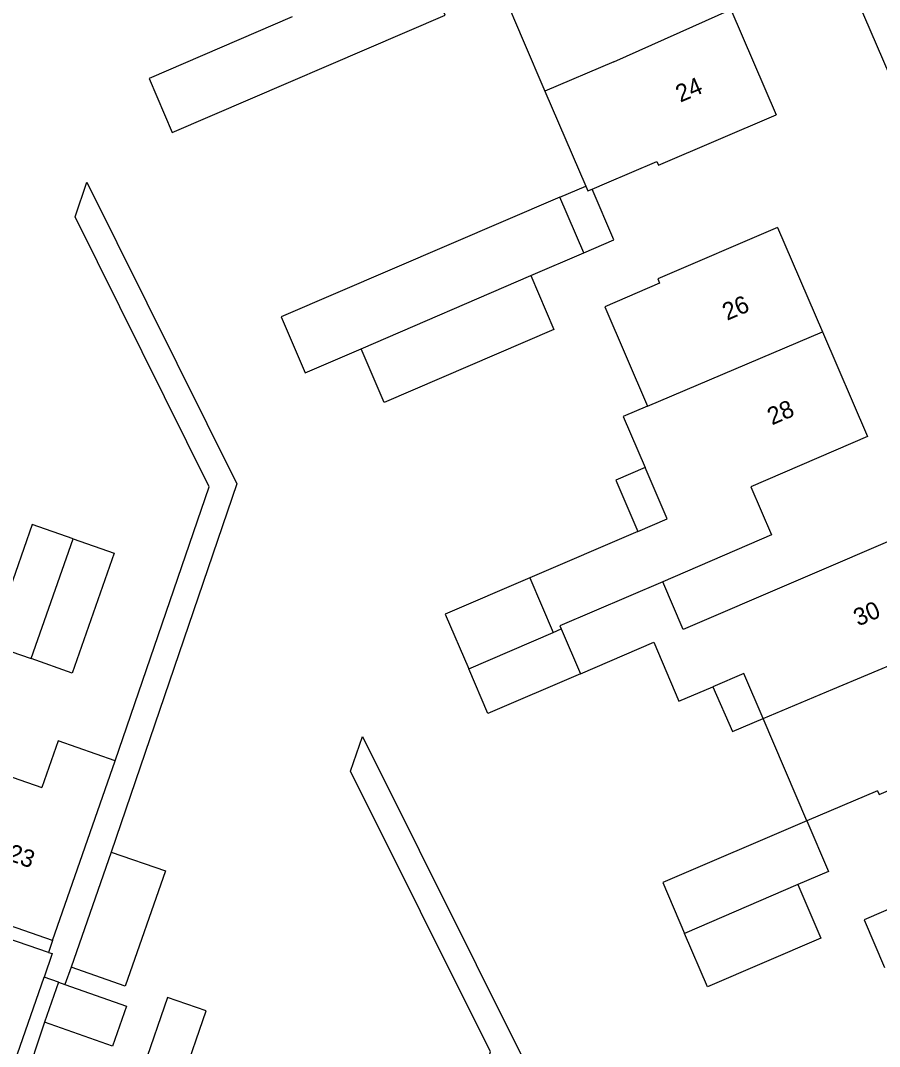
# Model space of a CAD drawing. Extents: x 136000 to 138005, y 398500 to 400500.
# Drawn here: x 137759.7 to 137809, y 398723.1 to 398782 of the extents above; entities that cross this region are included whole.
import ezdxf

# ---------------------------------------------------------------- set-up
doc = ezdxf.new("R2010")
doc.units = 0
for name, color, linetype in [('gg-afsc-erfafscheiding', 7, 'Continuous'), ('gg-afsc-muur', 7, 'Continuous'), ('gg-anno-huisnummerreeks BGT', 7, 'Continuous'), ('gg-bbg-bijgebouw', 7, 'Continuous'), ('gg-bbg-gedigitaliseerde bebouwing', 7, 'Continuous'), ('gg-bbg-gedigitaliseerde bijgebouw', 7, 'Continuous'), ('gg-bbg-hoofdgebouw', 7, 'Continuous'), ('gg-bbg-luifel en loopbrug', 7, 'Continuous'), ('gg-bbg-tussenscheiding', 7, 'Continuous'), ('gg-knt-verharding', 7, 'Continuous'), ('gt-grn-weggrens', 7, 'Continuous')]:
    doc.layers.add(name, color=color, linetype=linetype)

msp = doc.modelspace()

# ---------------------------------------------------------------- linework, layer by layer
at = {"layer": 'gg-afsc-erfafscheiding'}
for p, q in [((137761.51, 398729.22), (137761.274, 398728.544)), ((137762.565, 398727.688), (137762.218, 398726.693)), ((137761.844, 398726.825), (137761.017, 398727.113))]:
    msp.add_line(p, q, dxfattribs=at)
for points in [[(137765.103, 398739.532), (137770.498, 398755.248), (137762.793, 398770.748), (137763.477, 398772.741), (137772.079, 398755.436), (137764.868, 398734.298)], [(137782.084, 398709.586), (137786.635, 398722.844), (137778.609, 398738.936), (137779.292, 398740.927), (137795.591, 398708.25), (137794.909, 398706.255)]]:
    msp.add_lwpolyline(points, dxfattribs=at)
at = {"layer": 'gg-afsc-muur'}
msp.add_lwpolyline([(137761.038, 398724.538), (137759.872, 398721.019), (137759.911, 398721.006)], dxfattribs=at)
at = {"layer": 'gg-bbg-bijgebouw'}
for p, q in [((137764.868, 398734.298), (137762.565, 398727.688)), ((137761.844, 398726.825), (137761.038, 398724.538))]:
    msp.add_line(p, q, dxfattribs=at)
at = {"layer": 'gg-bbg-gedigitaliseerde bebouwing'}
for p, q in [((137788.523, 398780.863), (137789.767, 398777.965)), ((137789.767, 398777.965), (137792.108, 398772.515)), ((137792.47, 398772.336), (137793.308, 398772.696)), ((137795.086, 398752.699), (137788.892, 398750.034)), ((137788.892, 398750.034), (137790.239, 398746.902)), ((137790.239, 398746.902), (137790.699, 398747.1)), ((137790.699, 398747.1), (137791.804, 398744.528)), ((137791.804, 398744.528), (137796.004, 398746.334)), ((137804.793, 398736.087), (137802.282, 398741.955)), ((137808.842, 398737.82), (137804.793, 398736.087))]:
    msp.add_line(p, q, dxfattribs=at)
for points in [[(137797.85, 398788.67), (137791.048, 398785.736), (137791.199, 398785.383), (137787.301, 398783.709), (137788.523, 398780.863)], [(137793.308, 398772.696), (137796.182, 398773.931), (137796.274, 398773.716), (137803.03, 398776.61)], [(137792.108, 398772.515), (137792.229, 398772.233), (137792.47, 398772.336)], [(137803.11, 398770.14), (137796.236, 398767.19), (137796.343, 398766.942), (137793.203, 398765.592), (137795.654, 398759.891)], [(137795.654, 398759.891), (137794.258, 398759.291), (137795.519, 398756.359)], [(137795.086, 398752.699), (137796.78, 398753.428), (137795.519, 398756.359)], [(137796.004, 398746.334), (137797.452, 398742.949), (137799.391, 398743.778)], [(137802.282, 398741.955), (137801.169, 398744.543), (137799.391, 398743.778)], [(137758.609, 398740.655), (137758.924, 398740.545), (137758.345, 398738.891), (137760.889, 398738.001)], [(137765.103, 398739.532), (137761.821, 398740.676), (137760.889, 398738.001)], [(137808.842, 398737.82), (137808.936, 398737.6), (137815.8, 398740.54)], [(137818.17, 398735), (137811.316, 398732.065), (137811.409, 398731.846), (137808.077, 398730.416), (137809.251, 398727.682)]]:
    msp.add_lwpolyline(points, dxfattribs=at)
at = {"layer": 'gg-bbg-gedigitaliseerde bijgebouw'}
for p, q in [((137791.995, 398768.688), (137790.626, 398771.878)), ((137788.949, 398767.38), (137791.995, 398768.688)), ((137761.844, 398726.825), (137762.218, 398726.693))]:
    msp.add_line(p, q, dxfattribs=at)
for points in [[(137775.254, 398782.22), (137767.044, 398778.695), (137768.378, 398775.589), (137784.046, 398782.317), (137782.706, 398785.439)], [(137790.626, 398771.878), (137774.622, 398765.007), (137776.001, 398761.795), (137779.212, 398763.174)], [(137788.949, 398767.38), (137790.278, 398764.286), (137780.532, 398760.101), (137779.212, 398763.174)], [(137762.691, 398752.273), (137760.332, 398753.097), (137757.928, 398746.217), (137760.275, 398745.397)], [(137762.691, 398752.273), (137765.042, 398751.452), (137762.638, 398744.571), (137760.275, 398745.397)], [(137804.793, 398736.087), (137796.529, 398732.552), (137797.779, 398729.631)], [(137804.793, 398736.087), (137806.035, 398733.184), (137804.281, 398732.43)], [(137764.868, 398734.298), (137767.983, 398733.213), (137765.68, 398726.603), (137762.565, 398727.688)], [(137804.281, 398732.43), (137805.596, 398729.355), (137799.088, 398726.57), (137797.779, 398729.631)], [(137762.218, 398726.693), (137765.75, 398725.448), (137764.944, 398723.162), (137761.038, 398724.538)], [(137766.741, 398722.004), (137768.962, 398721.242), (137770.317, 398725.19), (137768.097, 398725.952), (137766.741, 398722.004)]]:
    msp.add_lwpolyline(points, dxfattribs=at)
at = {"layer": 'gg-bbg-hoofdgebouw'}
for p, q in [((137800.44, 398782.64), (137803.03, 398776.61)), ((137803.11, 398770.14), (137805.69, 398764.14)), ((137805.69, 398764.14), (137808.27, 398758.14)), ((137761.51, 398729.22), (137765.103, 398739.532))]:
    msp.add_line(p, q, dxfattribs=at)
for points in [[(137808.27, 398758.14), (137801.582, 398755.264), (137802.771, 398752.499), (137796.524, 398749.813)], [(137810.65, 398752.58), (137810.631, 398752.624), (137797.705, 398747.066), (137796.524, 398749.813)], [(137761.51, 398729.22), (137755.34, 398731.37), (137755.71, 398732.42)]]:
    msp.add_lwpolyline(points, dxfattribs=at)
at = {"layer": 'gg-bbg-luifel en loopbrug'}
for p, q in [((137790.626, 398771.878), (137792.108, 398772.515)), ((137785.39, 398744.816), (137790.239, 398746.902))]:
    msp.add_line(p, q, dxfattribs=at)
for points in [[(137791.995, 398768.688), (137793.719, 398769.428), (137792.47, 398772.336)], [(137795.519, 398756.359), (137793.825, 398755.631), (137795.086, 398752.699)], [(137788.892, 398750.034), (137784.043, 398747.948), (137785.39, 398744.816)], [(137791.804, 398744.528), (137786.495, 398742.245), (137785.39, 398744.816)], [(137799.391, 398743.778), (137800.534, 398741.207), (137802.282, 398741.955)]]:
    msp.add_lwpolyline(points, dxfattribs=at)
at = {"layer": 'gg-bbg-tussenscheiding'}
for p, q in [((137793.711, 398779.646), (137800.44, 398782.64)), ((137793.711, 398779.646), (137789.767, 398777.965)), ((137779.212, 398763.174), (137788.949, 398767.38)), ((137795.654, 398759.891), (137805.69, 398764.14)), ((137760.275, 398745.397), (137762.691, 398752.273)), ((137806.286, 398743.639), (137813.225, 398746.56)), ((137802.282, 398741.955), (137806.286, 398743.639)), ((137804.281, 398732.43), (137797.779, 398729.631))]:
    msp.add_line(p, q, dxfattribs=at)
msp.add_lwpolyline([(137796.524, 398749.813), (137790.622, 398747.279), (137790.699, 398747.1)], dxfattribs=at)
at = {"layer": 'gg-knt-verharding'}
msp.add_line((137860.962, 398659.111), (137807.709, 398783.153), dxfattribs=at)
for points in [[(137761.274, 398728.544), (137736.96, 398736.9), (137743.49, 398755.64), (137719.38, 398763.98), (137725.79, 398783.06), (137701.316, 398791.144), (137699.778, 398796.748)], [(137778.523, 398701.452), (137754.92, 398709.63), (137761.017, 398727.113)]]:
    msp.add_lwpolyline(points, dxfattribs=at)
at = {"layer": 'gt-grn-weggrens'}
msp.add_lwpolyline([(137761.274, 398728.544), (137761.49, 398728.47), (137761.017, 398727.113)], dxfattribs=at)

# ---------------------------------------------------------------- texts
at = {"layer": 'gg-anno-huisnummerreeks BGT'}
for s, rotation, p in [('24', 23.3, (137797.535, 398777.297)), ('26', 23.3, (137800.215, 398764.778)), ('28', 23.3, (137802.795, 398758.778)), ('30', 23.2, (137807.74, 398747.237)), ('23', 340.8, (137758.861, 398733.85))]:
    msp.add_text(s, height=1, rotation=rotation, dxfattribs=at).set_placement(p)

doc.saveas('drawing.dxf')
